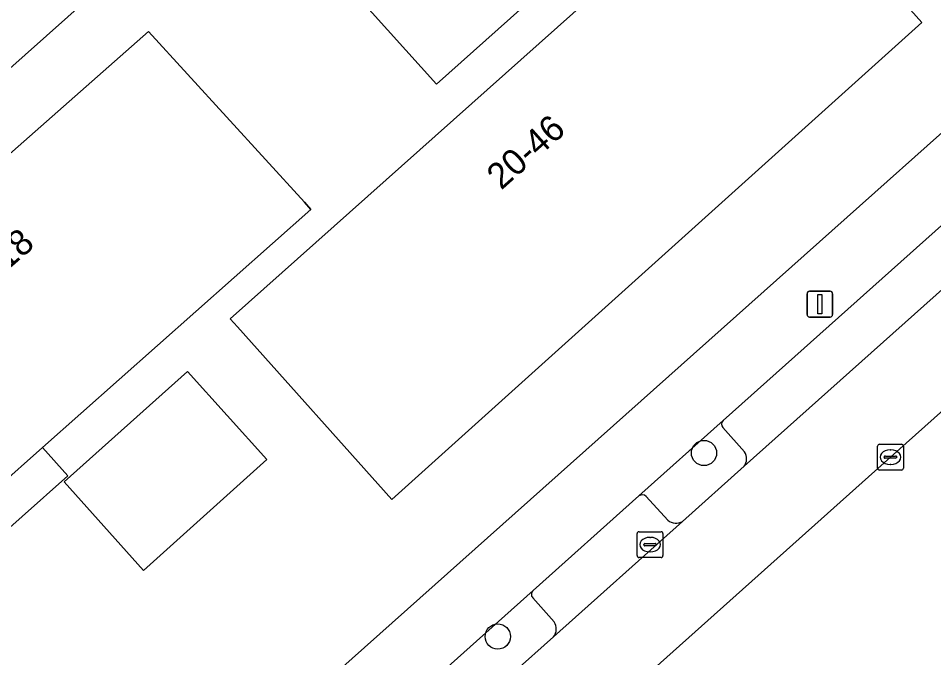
# Model space of a CAD drawing. Extents: x 162172 to 163187, y 382874 to 383685.
# Drawn here: x 162580.64 to 162616.09, y 383207.31 to 383232.09 of the extents above; entities that cross this region are included whole.
import ezdxf

# ---------------------------------------------------------------- set-up
doc = ezdxf.new("R2010")
doc.units = 0
for name, color, linetype in [('IMGEO_Boom', 7, 'Continuous'), ('IMGEO_Erf', 7, 'Continuous'), ('IMGEO_Groenvoorziening', 7, 'Continuous'), ('IMGEO_Kolk', 7, 'Continuous'), ('IMGEO_Lichtmast', 7, 'Continuous'), ('IMGEO_Pand', 7, 'Continuous'), ('IMGEO_Pand_nummerreeks', 7, 'Continuous'), ('IMGEO_Pand_overbouw', 7, 'Continuous'), ('IMGEO_Parkeervlak_open', 7, 'Continuous'), ('IMGEO_Rijbaan_lokaal_open', 7, 'Continuous'), ('IMGEO_Voetpad_open', 7, 'Continuous')]:
    doc.layers.add(name, color=color, linetype=linetype)

msp = doc.modelspace()

# ---------------------------------------------------------------- linework, layer by layer
at = {"layer": 'IMGEO_Boom'}
for centre in [(162607.195, 383215.244), (162599.207, 383208.131)]:
    msp.add_circle(centre, 0.489, dxfattribs=at)
at = {"layer": 'IMGEO_Erf'}
for points in [[(162586.39, 383200.872), (162588.21, 383202.497), (162641.443, 383250)], [(162586.091, 383235.314), (162568.622, 383219.741), (162584.749, 383200.98)]]:
    msp.add_lwpolyline(points, dxfattribs=at)
for points in [[(162609.459, 383238.834), (162609.726, 383238.535), (162615.634, 383231.921), (162595.098, 383213.44), (162589.127, 383220.13), (162588.848, 383220.443)], [(162593.753, 383232.971), (162598.559, 383237.213), (162601.612, 383233.816), (162596.828, 383229.54)], [(162578.021, 383212.3), (162571.72, 383219.265), (162585.677, 383231.574), (162591.716, 383224.96), (162591.966, 383224.686), (162581.578, 383215.46)], [(162590.257, 383214.996), (162585.48, 383210.692), (162582.413, 383214.123), (162587.192, 383218.399)]]:
    msp.add_lwpolyline(points, close=True, dxfattribs=at)
at = {"layer": 'IMGEO_Groenvoorziening'}
msp.add_lwpolyline([(162718.775, 383301.078), (162715.908, 383302.61), (162713.445, 383303.655), (162712.478, 383302.8), (162711.785, 383302.188), (162708.036, 383298.826), (162691.32, 383283.864), (162676.816, 383270.908), (162663.821, 383259.29), (162646.358, 383243.687), (162640.771, 383238.704), (162631.839, 383230.648), (162614.417, 383215.084), (162598.429, 383200.785), (162594.538, 383197.307), (162593.832, 383196.676), (162592.898, 383195.841), (162594.073, 383194.754)], dxfattribs=at)
at = {"layer": 'IMGEO_Kolk'}
for p, q in [((162613.916, 383214.658), (162613.916, 383215.51)), ((162613.991, 383215.584), (162614.843, 383215.584)), ((162614.404, 383215.364), (162614.429, 383215.364)), ((162614.917, 383215.51), (162614.917, 383214.658)), ((162614.175, 383215.078), (162614.175, 383215.09)), ((162614.613, 383215.041), (162614.215, 383215.041)), ((162614.218, 383215.127), (162614.616, 383215.127)), ((162614.659, 383215.09), (162614.659, 383215.078)), ((162614.843, 383214.584), (162613.991, 383214.584)), ((162614.427, 383214.804), (162614.402, 383214.804)), ((162604.604, 383211.268), (162604.604, 383212.12)), ((162604.679, 383212.194), (162605.531, 383212.194)), ((162605.605, 383212.12), (162605.605, 383211.268)), ((162604.906, 383211.737), (162605.304, 383211.737)), ((162605.092, 383211.974), (162605.117, 383211.974)), ((162604.863, 383211.688), (162604.863, 383211.7)), ((162605.301, 383211.651), (162604.903, 383211.651)), ((162605.115, 383211.414), (162605.09, 383211.414)), ((162605.347, 383211.7), (162605.347, 383211.688)), ((162605.531, 383211.194), (162604.679, 383211.194))]:
    msp.add_line(p, q, dxfattribs=at)
for points in [[(162613.916, 383214.658), (162613.916, 383215.51)], [(162613.991, 383215.584), (162614.843, 383215.584)], [(162614.917, 383215.51), (162614.917, 383214.658)], [(162614.843, 383214.584), (162613.991, 383214.584)], [(162604.604, 383211.268), (162604.604, 383212.12)], [(162604.679, 383212.194), (162605.531, 383212.194)], [(162605.605, 383212.12), (162605.605, 383211.268)], [(162605.531, 383211.194), (162604.679, 383211.194)]]:
    msp.add_lwpolyline(points, dxfattribs=at)
for centre, radius, start, end in [((162613.993, 383215.508), 0.0765, 91.552, 178.448), ((162613.993, 383215.508), 0.0765, 91.552, 178.448), ((162614.841, 383215.508), 0.0765, 1.552, 88.448), ((162614.841, 383215.508), 0.0765, 1.552, 88.448), ((162614.215, 383215.087), 0.0403, 85.8775, 175.7526), ((162614.212, 383215.077), 0.0366, 178.938, 274.7102), ((162614.616, 383215.084), 0.043, 264.8664, 352.4533), ((162614.62, 383215.089), 0.0386, 1.7309, 96.639), ((162613.993, 383214.66), 0.0765, 181.552, 268.448), ((162613.993, 383214.66), 0.0765, 181.552, 268.448), ((162614.841, 383214.66), 0.0765, 271.552, 358.448), ((162614.841, 383214.66), 0.0765, 271.552, 358.448), ((162604.681, 383212.118), 0.0765, 91.552, 178.448), ((162604.681, 383212.118), 0.0765, 91.552, 178.448), ((162605.529, 383212.118), 0.0765, 1.552, 88.448), ((162605.529, 383212.118), 0.0765, 1.552, 88.448), ((162604.903, 383211.697), 0.0403, 85.8775, 175.7526), ((162605.308, 383211.699), 0.0386, 1.7309, 96.639), ((162604.9, 383211.687), 0.0366, 178.938, 274.7102), ((162605.304, 383211.694), 0.043, 264.8664, 352.4533), ((162604.681, 383211.27), 0.0765, 181.552, 268.448), ((162604.681, 383211.27), 0.0765, 181.552, 268.448), ((162605.529, 383211.27), 0.0765, 271.552, 358.448), ((162605.529, 383211.27), 0.0765, 271.552, 358.448)]:
    msp.add_arc(centre, radius, start, end, dxfattribs=at)
for centre, major_axis, ratio, start_param, end_param in [((162614.403, 383215.084), (-0.387, 0.002), 0.722429, 4.712389, 7.853982), ((162614.428, 383215.084), (-0.39, 0.002), 0.717154, 1.570796, 4.712389), ((162605.091, 383211.694), (-0.387, 0.002), 0.722429, 4.712389, 7.853982), ((162605.116, 383211.694), (-0.39, 0.002), 0.717154, 1.570796, 4.712389)]:
    msp.add_ellipse(centre, major_axis=major_axis, ratio=ratio, start_param=start_param, end_param=end_param, dxfattribs=at)
at = {"layer": 'IMGEO_Lichtmast'}
for p, q in [((162611.187, 383220.614), (162611.187, 383221.414)), ((162611.187, 383221.414), (162611.187, 383220.614)), ((162611.287, 383221.514), (162612.077, 383221.514)), ((162612.077, 383221.514), (162611.287, 383221.514)), ((162612.177, 383221.414), (162612.177, 383220.614)), ((162612.177, 383220.614), (162612.177, 383221.414)), ((162612.077, 383220.514), (162611.287, 383220.514)), ((162611.287, 383220.514), (162612.077, 383220.514))]:
    msp.add_line(p, q, dxfattribs=at)
msp.add_lwpolyline([(162611.607, 383221.389), (162611.757, 383221.389), (162611.757, 383220.639), (162611.607, 383220.639), (162611.607, 383221.389)], dxfattribs=at)
for centre, start, end in [((162611.287, 383221.414), 90, 180), ((162611.287, 383221.414), 90, 180), ((162612.077, 383221.414), 0, 90), ((162612.077, 383221.414), 360, 90), ((162611.287, 383220.614), 180, 270), ((162611.287, 383220.614), 180, 270), ((162612.077, 383220.614), 270, 0), ((162612.077, 383220.614), 270, 0)]:
    msp.add_arc(centre, 0.1, start, end, dxfattribs=at)
at = {"layer": 'IMGEO_Pand'}
for points in [[(162609.726, 383238.535), (162609.459, 383238.834), (162588.848, 383220.443), (162589.127, 383220.13), (162595.098, 383213.44), (162615.634, 383231.921)], [(162596.828, 383229.54), (162601.612, 383233.816), (162598.559, 383237.213), (162593.753, 383232.971)], [(162591.966, 383224.686), (162591.716, 383224.96), (162585.677, 383231.574), (162571.72, 383219.265), (162578.021, 383212.3), (162581.578, 383215.46)], [(162582.413, 383214.123), (162585.48, 383210.692), (162590.257, 383214.996), (162587.192, 383218.399)]]:
    msp.add_lwpolyline(points, close=True, dxfattribs=at)
at = {"layer": 'IMGEO_Pand_overbouw'}
msp.add_lwpolyline([(162582.553, 383214.363), (162581.578, 383215.46), (162578.021, 383212.3), (162579.005, 383211.212)], close=True, dxfattribs=at)
at = {"layer": 'IMGEO_Parkeervlak_open'}
for points in [[(162616.51, 383224.164), (162607.933, 383216.501)], [(162608.746, 383214.728), (162618.227, 383223.191)], [(162607.92, 383216.227), (162608.768, 383215.286)], [(162604.674, 383213.579), (162600.573, 383209.92)], [(162605.789, 383212.64), (162604.956, 383213.564)], [(162601.371, 383208.121), (162606.368, 383212.592)], [(162600.56, 383209.634), (162601.392, 383208.699)]]:
    msp.add_lwpolyline(points, dxfattribs=at)
for centre, radius, start, end in [((162608.075, 383216.357), 0.202, 134.556, 220.0112), ((162608.349, 383215.023), 0.495, 323.3649, 32.1195), ((162604.806, 383213.393), 0.228, 48.6186, 125.2919), ((162606.114, 383213.042), 0.517, 231.0928, 299.4291), ((162600.709, 383209.771), 0.202, 132.261, 222.5339), ((162600.956, 383208.425), 0.515, 323.7617, 32.0768)]:
    msp.add_arc(centre, radius, start, end, dxfattribs=at)
at = {"layer": 'IMGEO_Rijbaan_lokaal_open'}
msp.add_lwpolyline([(162618.227, 383223.191), (162608.746, 383214.728), (162606.368, 383212.592), (162601.371, 383208.121), (162598.236, 383205.326), (162593.254, 383200.868), (162592.209, 383199.929), (162594.538, 383197.307), (162598.429, 383200.785), (162614.417, 383215.084), (162631.839, 383230.648)], dxfattribs=at)
at = {"layer": 'IMGEO_Voetpad_open'}
for points in [[(162641.443, 383250), (162588.21, 383202.497), (162586.39, 383200.872), (162589.111, 383197.155), (162591.159, 383198.992), (162590.019, 383200.615), (162592.455, 383202.662), (162596.549, 383206.31), (162600.573, 383209.92), (162604.674, 383213.579), (162607.933, 383216.501), (162616.51, 383224.164)], [(162584.072, 383237.596), (162566.646, 383222.046), (162568.622, 383219.741), (162586.091, 383235.314)], [(162607.933, 383216.501), (162604.674, 383213.579)], [(162608.768, 383215.286), (162607.92, 383216.227)], [(162606.368, 383212.592), (162608.746, 383214.728)], [(162604.956, 383213.564), (162605.789, 383212.64)], [(162600.573, 383209.92), (162596.549, 383206.31)], [(162601.392, 383208.699), (162600.56, 383209.634)], [(162598.236, 383205.326), (162601.371, 383208.121)]]:
    msp.add_lwpolyline(points, dxfattribs=at)
for centre, radius, start, end in [((162608.075, 383216.357), 0.202, 134.556, 220.0112), ((162608.349, 383215.023), 0.495, 323.3649, 32.1195), ((162604.806, 383213.393), 0.228, 48.6186, 125.2919), ((162606.114, 383213.042), 0.517, 231.0928, 299.4291), ((162600.709, 383209.771), 0.202, 132.261, 222.5339), ((162600.956, 383208.425), 0.515, 323.7617, 32.0768)]:
    msp.add_arc(centre, radius, start, end, dxfattribs=at)

# ---------------------------------------------------------------- texts
at = {"layer": 'IMGEO_Pand_nummerreeks'}
for s, rotation, p in [('20-46', 41.7422, (162599.34, 383225.409)), ('2-18', 40.9894, (162579.302, 383221.518))]:
    msp.add_text(s, height=1, rotation=rotation, dxfattribs=at).set_placement(p)

doc.saveas('drawing.dxf')
